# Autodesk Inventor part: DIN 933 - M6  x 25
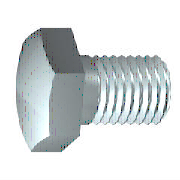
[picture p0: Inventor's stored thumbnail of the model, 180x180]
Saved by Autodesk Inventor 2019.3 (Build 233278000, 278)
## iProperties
Created: 2018-01
Part Number: DIN 933 - M6  x 25
Material: Ocel, měkká
Description: Šestihranný šroub
Document SubType Name: Modeling
Standard: DIN 933
Designer: B-hon
Standards Organization: DIN
Language: cs-CZ
Size Designation: M6  x 25
Categories: <MemberInstance><Categories><Category DisplayName="Spojovací materiál" InternalName="e4da775c-781d-43d5-af7c-5136215cf5a6" Mnemonic="FSTN"><Category DisplayName
Density: 7.85 g/cm^3
Appearance: Pololeštěná
IsCustomPart: 0
Author: B-hon
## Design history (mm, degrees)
sketch "Náčrt1"
  geometry: L1 (0, 4.35)-(0, 2.729); L2 (3, 3)-(25, 3); L3 (25, 3)-(25, 0); L4 (25, 0)-(-0.5, 0); L5 (-5.6, 0)-(30.1, 0) reference; L6 (-0.5, 0)-(-0.5, 4.35); L7 (-0.5, 4.35)-(0, 4.35); L8 (3, 3)-(2.386, 2.729); L9 (2.386, 2.729)-(0, 2.729); L10 (0, -0.87)-(0, 5.22) reference
  constraints: 16 end point, 2 collinear, 2 perpendicular, 1 parallel
  dimensions: "d0" = 25 distance between parallel lines of L3 L1 (= NLG); "d1" = 22 distance from line of L2.start L3 (= GEL); "d2" = 6 diameter of L2 L4 (= GD); "d9" = 0.5001 distance between parallel lines of L6 L1 (computed from SD); "d10" = 8.7 diameter of L7 L4 (= SD2); "d13" = 0.61355 horizontal distance of L2.start L8.end (computed from GAL); "d14" = 5.45873 diameter of L9 L4 (= BDM)
revolve "Těleso" sketch "Náčrt1" stored, may be unused: angle "d12" = 90 deg
sketch "Náčrt2"
  geometry: L1 (0, 5.774)-(5, 2.887); L2 (5, 2.887)-(5, -2.887); L3 (5, -2.887)-(0, -5.774); L4 (0, -5.774)-(-5, -2.887); L5 (-5, -2.887)-(-5, 2.887); L6 (-5, 2.887)-(0, 5.774); 2 further points
  constraints: 12 end point, 1 coincident, 1 vertical, 11 other
  dimensions: "d11" = 10 distance between parallel lines of L5 L2 (= SW)
extrude "Hlava" join sketch "Náčrt2" distance "d3" = 3.5 (= KOH - SD); taper "d4" = 0 deg
sketch "Náčrt4"
  geometry: L1 (-4, 5)-(-4, 5.774); L2 (-4, 5.774)-(-3.554, 5.774); L3 (-3.554, 5.774)-(-4, 5); L4 (-4.7, 0)-(0.2, 0) reference; L5 (-0.5, 5.774)-(-4, 5.774) reference; L6 (-4, 2.887)-(-4, 5.774) reference
  constraints: 6 end point, 2 collinear, 1 perpendicular, 1 vertical
  dimensions: "d5" = 30 deg angle of L3 L1 (= ANG1); "d19" = 10 diameter of L1.start L4 (= SW0)
revolve "Zkosení1" sketch "Náčrt4" stored, may be unused: angle "d21" = 90 deg
workplane "Work Plane1"
body "Solid1"
feature "Závit" dims "d15" = 22 (= GEL), "d16" = 0
chamfer "Zkosení2" distance "d6" = 0.61345 (= -0.5 x SPD + 0.5 x GD); stored, may be unused: second distance "d7" = 0.61355 (computed from GUL), angle "d55" = 45 deg
other parameters: "NLG" = 25 [user parameter; used in 1 equation term], "GD" = 6 (= NND) [user parameter; used in 2 equation terms], "BDM" = 5.45873 [user parameter; used in 1 equation term], "KOH" = 4 [user parameter; used in 1 equation term], "GEL" = 22 [user parameter; used in 2 equation terms], "SW" = 10 [user parameter; used in 2 equation terms], "SW0" = 10 [user parameter; used in 1 equation term], "SPD" = 4.7731 (= NND - 1.2269 x PTC) [user parameter; used in 1 equation term], "SD2" = 8.7 [user parameter; used in 1 equation term], "SD" = 0.5 [user parameter; used in 2 equation terms], "ANG1" = 30 deg [user parameter; used in 1 equation term], "GAL" = 0.61345 (= 0.61345 x PTC) [user parameter; used in 1 equation term], "GUL" = 0.61345 (= 0.61345 x PTC) [user parameter; used in 1 equation term], "d8" = 0, "RR" = 0.25 [user parameter], "d57" = 0, "d58" = 0, "GD1" = 4.7731 (= THREADDIA - 1.2269 x PTC) [user parameter], "THREADDIA" = 6 [user parameter; used in 1 equation term], "TOA" = 30 deg [user parameter], "PTC" = 1 [user parameter; used in 5 equation terms], "NND" = 6 [user parameter; used in 2 equation terms], "E0" = 11.55 (= 1.155 x SW) [user parameter]
